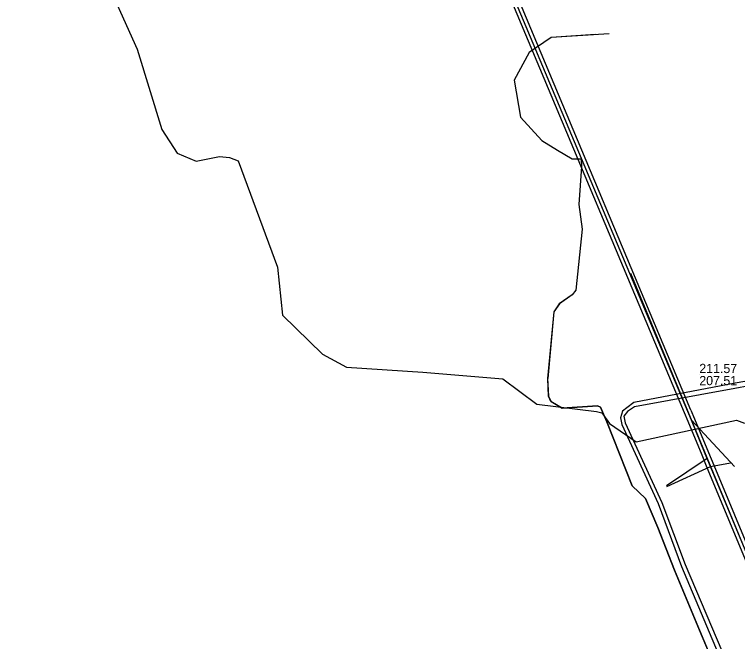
# Model space of a CAD drawing. Extents: x -595540 to -593988, y -1160850 to -1159202.
# Drawn here: x -595381.9 to -595319.4, y -1160577.1 to -1160522.8 of the extents above; entities that cross this region are included whole.
import ezdxf

# ---------------------------------------------------------------- set-up
doc = ezdxf.new("R2010")
doc.units = 0
for name, color, linetype in [('BKOM-ODVODNENI_trasa sítě', 7, 'Continuous'), ('BVK-JEDNOTNA_popisy', 7, 'Continuous'), ('BVK-JEDNOTNA_trasa sítě', 7, 'Continuous'), ('BVK-JEDNOTNA_trasa sítě obvodem', 7, 'Continuous'), ('CETIN_kabel podzemní', 7, 'Continuous'), ('DESTOVA_trasa neprovozované sítě', 7, 'Continuous'), ('DSP-SDEL-VODAFONE_kabel', 7, 'Continuous'), ('EON-VN_kabel', 7, 'Continuous'), ('QUANTCOM_kabel', 7, 'Continuous')]:
    doc.layers.add(name, color=color, linetype=linetype)

msp = doc.modelspace()

# ---------------------------------------------------------------- linework, layer by layer
at = {"layer": 'BKOM-ODVODNENI_trasa sítě'}
for points in [[(-595328.652, -1160545.194), (-595323.701, -1160557.168), (-595307.991, -1160595.166), (-595289.318, -1160637.909), (-595269.901, -1160680.144), (-595243.565, -1160700.938), (-595203.101, -1160731.684), (-595169.808, -1160756.776), (-595134.211, -1160783.069), (-595091.899, -1160806.063), (-595046.729, -1160830.268), (-595023.064, -1160843.241)], [(-595325.53, -1160563.56), (-595322.03, -1160561.2)], [(-595321.73, -1160561.94), (-595320.01, -1160561.6)]]:
    msp.add_lwpolyline(points, dxfattribs=at)
at = {"layer": 'BVK-JEDNOTNA_popisy'}
msp.add_line((-595322.7, -1160553.968), (-595322.7, -1160553.968), dxfattribs=at)
at = {"layer": 'BVK-JEDNOTNA_trasa sítě'}
msp.add_line((-595323.7, -1160557.168), (-595358.62, -1160473.91), dxfattribs=at)
msp.add_lwpolyline([(-595307.848, -1160595.29), (-595321.729, -1160561.938), (-595322.189, -1160560.825), (-595323.389, -1160557.923), (-595323.701, -1160557.168)], dxfattribs=at)
at = {"layer": 'BVK-JEDNOTNA_trasa sítě obvodem'}
for p, q in [((-595323.977, -1160557.284), (-595358.897, -1160474.026)), ((-595323.423, -1160557.052), (-595358.343, -1160473.794))]:
    msp.add_line(p, q, dxfattribs=at)
for points in [[(-595308.125, -1160595.405), (-595322.006, -1160562.053), (-595322.466, -1160560.939), (-595323.666, -1160558.038), (-595323.978, -1160557.283)], [(-595323.424, -1160557.053), (-595323.112, -1160557.808), (-595321.912, -1160560.71), (-595321.452, -1160561.823), (-595307.571, -1160595.175)]]:
    msp.add_lwpolyline(points, dxfattribs=at)
at = {"layer": 'CETIN_kabel podzemní'}
msp.add_lwpolyline([(-595330.51, -1160524.47), (-595335.51, -1160524.8), (-595337.42, -1160526.1), (-595338.71, -1160528.5), (-595338.17, -1160531.69), (-595336.31, -1160533.72), (-595334.97, -1160534.56), (-595333.71, -1160535.29), (-595332.93, -1160535.29), (-595332.88, -1160535.95), (-595333.13, -1160539.24), (-595332.84, -1160541.38), (-595333.37, -1160546.67), (-595333.69, -1160547.07), (-595334.81, -1160547.86), (-595335.3, -1160548.55), (-595335.82, -1160554.31), (-595335.75, -1160555.83), (-595335.53, -1160556.3), (-595334.57, -1160556.89), (-595331.52, -1160556.68), (-595331.24, -1160556.8), (-595330.71, -1160558.07), (-595328.5, -1160563.59), (-595327.36, -1160564.7), (-595326.29, -1160567.22), (-595324.86, -1160570.9), (-595322.68, -1160576.09), (-595320.19, -1160582.02)], dxfattribs=at)
at = {"layer": 'DESTOVA_trasa neprovozované sítě'}
for p, q in [((-595319.66, -1160561.94), (-595323.389, -1160557.923)), ((-595325.52, -1160563.664), (-595321.729, -1160561.938))]:
    msp.add_line(p, q, dxfattribs=at)
at = {"layer": 'DSP-SDEL-VODAFONE_kabel'}
msp.add_line((-595324.855, -1160570.9), (-595326.289, -1160567.222), dxfattribs=at)
for points in [[(-595331.667, -1160524.55), (-595335.507, -1160524.802), (-595337.421, -1160526.099), (-595338.707, -1160528.495), (-595338.168, -1160531.685), (-595336.314, -1160533.716), (-595334.97, -1160534.561), (-595333.714, -1160535.294), (-595332.93, -1160535.287), (-595332.882, -1160535.954), (-595333.129, -1160539.241), (-595332.838, -1160541.377)], [(-595332.838, -1160541.377), (-595333.369, -1160546.665), (-595333.692, -1160547.067), (-595334.809, -1160547.859), (-595335.296, -1160548.55), (-595335.817, -1160554.313)], [(-595326.289, -1160567.222), (-595327.364, -1160564.699), (-595328.5, -1160563.589), (-595330.708, -1160558.071), (-595331.241, -1160556.8), (-595331.518, -1160556.678), (-595334.572, -1160556.888), (-595335.531, -1160556.298), (-595335.753, -1160555.834), (-595335.817, -1160554.313)], [(-595322.678, -1160576.088), (-595324.855, -1160570.9)], [(-595315.571, -1160591.984), (-595316.315, -1160592.071), (-595320.188, -1160582.024), (-595322.678, -1160576.088)]]:
    msp.add_lwpolyline(points, dxfattribs=at)
at = {"layer": 'EON-VN_kabel'}
for points in [[(-595285.707, -1160545.727), (-595286.113, -1160545.675), (-595286.621, -1160545.926), (-595286.894, -1160546.444), (-595286.705, -1160547.376), (-595286.581, -1160547.799), (-595286.779, -1160547.914), (-595294.325, -1160550.552), (-595297.486, -1160551.056), (-595303.71, -1160552.305), (-595312.244, -1160553.433), (-595319.598, -1160554.703), (-595328.37, -1160556.389), (-595328.972, -1160556.86), (-595329.354, -1160557.126), (-595329.528, -1160557.729), (-595329.414, -1160558.295), (-595326.258, -1160565.131), (-595324.247, -1160570.598), (-595320.619, -1160579.212), (-595317.228, -1160586.437), (-595317.047, -1160587.999)], [(-595285.75, -1160546.034), (-595286.145, -1160546.104), (-595286.391, -1160546.232), (-595286.57, -1160546.576), (-595286.332, -1160547.376), (-595286.241, -1160547.95), (-595286.591, -1160548.147), (-595294.377, -1160550.903), (-595297.411, -1160551.29), (-595303.691, -1160552.628), (-595312.195, -1160553.786), (-595319.616, -1160555.189), (-595328.302, -1160556.766), (-595328.924, -1160557.174), (-595329.23, -1160557.574), (-595329.1, -1160558.162), (-595325.955, -1160565.059), (-595323.93, -1160570.417), (-595320.264, -1160579.032), (-595316.959, -1160586.319), (-595316.8, -1160588.015)]]:
    msp.add_lwpolyline(points, dxfattribs=at)
at = {"layer": 'QUANTCOM_kabel'}
for points in [[(-595431.72, -1160417.22), (-595431.61, -1160417.96), (-595431.28, -1160420.2), (-595402.37, -1160439.02), (-595401.36, -1160440.28), (-595398.13, -1160447.59), (-595396.94, -1160452.53), (-595396.15, -1160453.56), (-595395.28, -1160454.44), (-595394.39, -1160457.38), (-595394.07, -1160461.6), (-595393, -1160465.82), (-595390.62, -1160470.7), (-595387.11, -1160481.89), (-595381.57, -1160497.41), (-595377.36, -1160510.45), (-595374.49, -1160518.79), (-595371.34, -1160525.81), (-595369.2, -1160532.75), (-595367.86, -1160534.81), (-595366.24, -1160535.5), (-595364.2, -1160535.11)], [(-595364.2, -1160535.11), (-595363.35, -1160535.19), (-595362.59, -1160535.47), (-595359.2, -1160544.69), (-595358.77, -1160548.82), (-595355.29, -1160552.2), (-595353.21, -1160553.33), (-595346.63, -1160553.76), (-595339.7, -1160554.33), (-595336.75, -1160556.53), (-595331.6, -1160557.16), (-595331.13, -1160557.27), (-595330.47, -1160558.21), (-595328.17, -1160559.8), (-595319.48, -1160557.92), (-595318.78, -1160558.18)]]:
    msp.add_lwpolyline(points, dxfattribs=at)

# ---------------------------------------------------------------- texts
at = {"layer": 'BVK-JEDNOTNA_popisy'}
for s, p in [('211.57', (-595322.7, -1160553.843)), ('207.51', (-595322.7, -1160554.893))]:
    msp.add_text(s, height=0.8, dxfattribs=at).set_placement(p)

doc.saveas('drawing.dxf')
